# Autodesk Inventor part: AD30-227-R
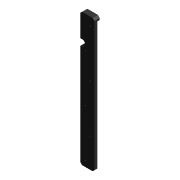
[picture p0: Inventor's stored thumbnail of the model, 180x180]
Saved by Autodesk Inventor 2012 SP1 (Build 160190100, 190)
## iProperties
Shininess: 0.0
Created: 2000-06
Part Number: AD30-227-R
Description: GUIDE RAIL
Document SubType Name: Modeling
Designer: Ron
Material: Delrin, Black
Density: 1.425 g/cm^3
Density: 0.0
Volumn: 0.0
Area: 0.0
PropertySet Name: Model Information
Control State: 0
Master: False
Checked Out: False
Title: GUIDE RAIL
Author: Ron
Revision Number: 01
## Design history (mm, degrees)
derived "lower left guide rail.ipt"
body "Solid1"
node "TaggingFeature2"
feature "Solid1::lower left guide rail.ipt" dims "d0" = 10
